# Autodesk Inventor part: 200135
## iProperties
Created: 2007-11
Part Number: 200135
Document SubType Name: Modeling
Designer: JJ
Density: 1.06 g/cm^3
Mass: 15.4479 g
Surface Area: 94.4063 cm^2
Volume: 14.5735 cm^3
Material: ABS Plastic
Description: GEAR  HOUSING CASE SIDE 2
Component Category: Lower Component
Author: JJ
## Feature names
1. Extrusion1
2. Extrusion2
3. Extrusion3
4. Extrusion4
5. Extrusion5
6. Extrusion6
7. Revolution1
8. Split1
9. Extrusion7
10. Extrusion8
11. Fillet7
12. Fillet8
13. Fillet9
14. Extrusion9
15. Extrusion11
16. Hole2
17. Chamfer1
18. Fillet13
19. Fillet14
20. Fillet15
21. Mirror1
